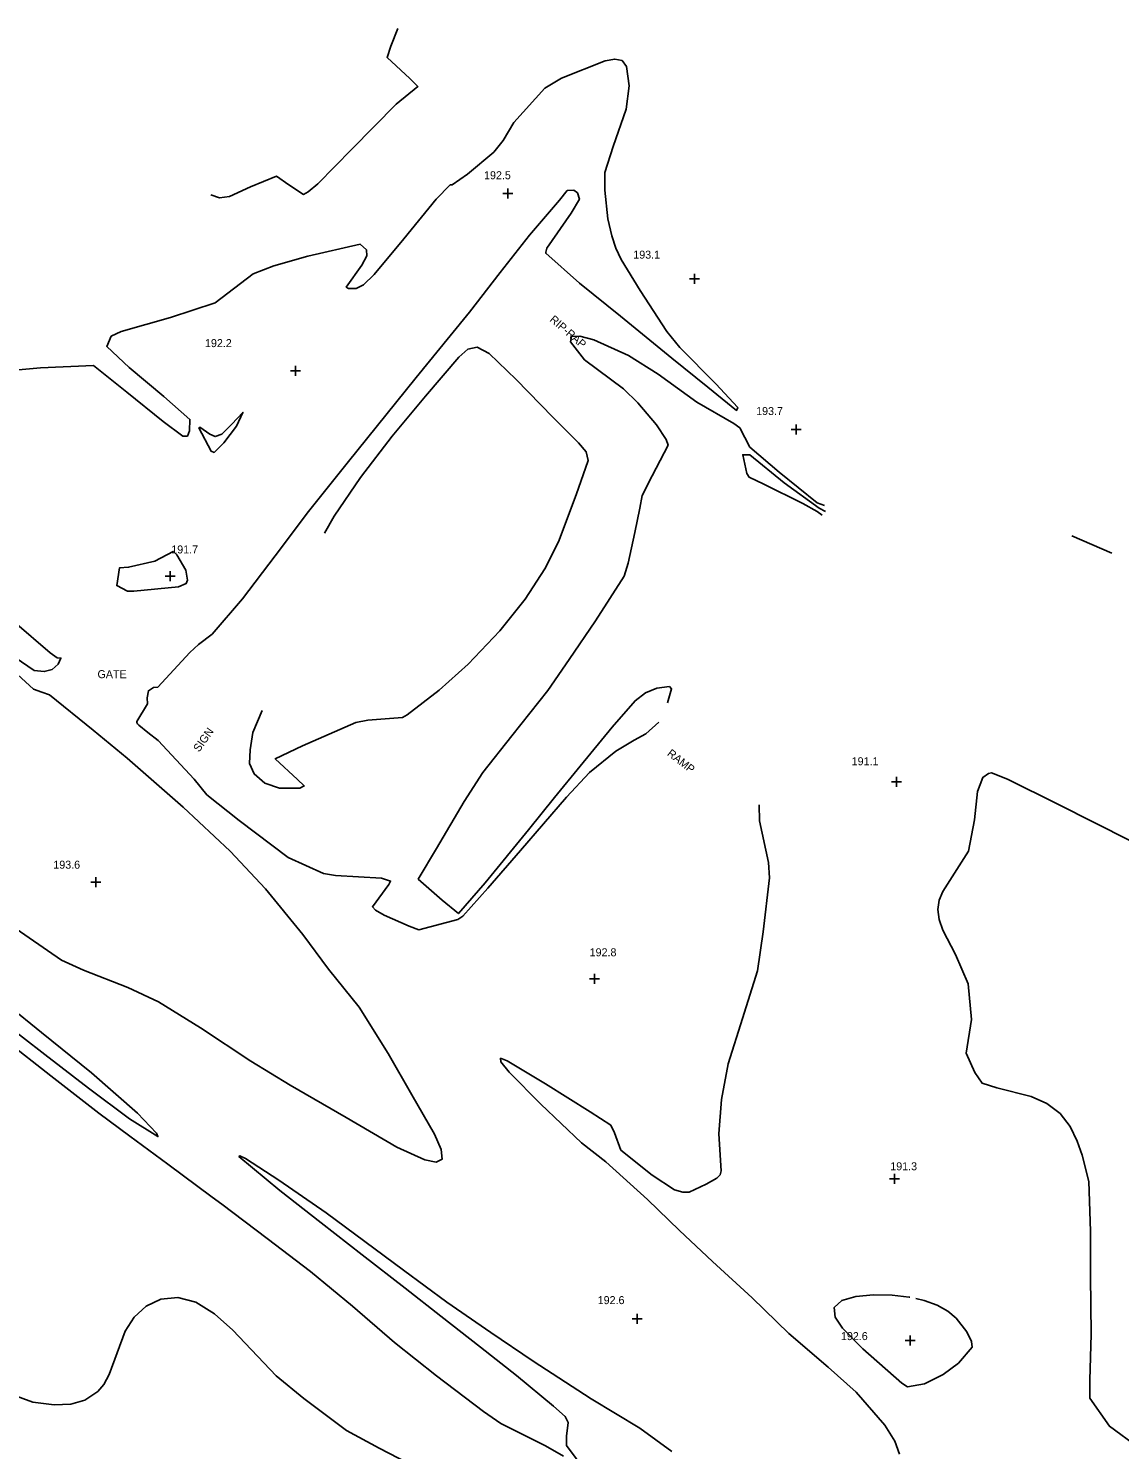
# Model space of a CAD drawing. Extents: x 1467615 to 2003689, y 770235 to 1108726.
# Drawn here: x 1994958.5 to 1995231.2, y 777132.3 to 777487.6 of the extents above; entities that cross this region are included whole.
import ezdxf

# ---------------------------------------------------------------- set-up
doc = ezdxf.new("R2010")
doc.units = 0
for name, color, linetype in [('RD_DTM_Minor1', 7, 'Continuous'), ('RD_DTM_Spot_Elev', 7, 'Continuous'), ('RD_TX_Misc1', 7, 'Continuous')]:
    doc.layers.add(name, color=color, linetype=linetype)

msp = doc.modelspace()

# ---------------------------------------------------------------- linework, layer by layer
at = {"layer": 'RD_DTM_Minor1'}
msp.add_line((1995219.32, 777360.71), (1995229.32, 777356.41), dxfattribs=at)
for points in [[(1995004.03, 777446.02), (1995006.26, 777445.24), (1995008.73, 777445.59), (1995013.96, 777448.01), (1995020.46, 777450.62), (1995023.59, 777448.46), (1995027.25, 777446.08), (1995028.37, 777446.72), (1995030.78, 777448.76), (1995039.35, 777457.45), (1995050.38, 777468.67), (1995055.83, 777473.11), (1995053.81, 777475.05), (1995048.11, 777480.32), (1995049.04, 777483.2), (1995050.78, 777487.59)], [(1994948.53, 777401.56), (1994961.49, 777402.72), (1994974.76, 777403.29), (1994983.11, 777396.65), (1994992.14, 777389.34), (1994997.1, 777385.68), (1994998.21, 777385.63), (1994998.77, 777386.96), (1994998.85, 777389.86), (1994992.35, 777395.6), (1994983.64, 777402.82), (1994978.07, 777408.08), (1994979.19, 777410.64), (1994981.62, 777411.82), (1994993.95, 777415.34), (1995005.14, 777418.99), (1995014.62, 777426.25), (1995019.85, 777428.27), (1995028.32, 777430.67), (1995041.38, 777433.62), (1995042.99, 777432.23), (1995043.1, 777430.73), (1995041.81, 777428.45), (1995037.91, 777422.92), (1995038.5, 777422.58), (1995040.42, 777422.59), (1995042.27, 777423.5), (1995044.9, 777426.06), (1995052.35, 777434.98), (1995060.44, 777444.88), (1995063.9, 777448.49), (1995064.37, 777448.52), (1995068.23, 777451.12), (1995074.81, 777456.65), (1995077.12, 777459.59), (1995079.83, 777464.09), (1995087.55, 777472.7), (1995091.72, 777475.2), (1995102.67, 777479.46), (1995105.03, 777479.95), (1995106.89, 777479.56), (1995108.01, 777478.04), (1995108.61, 777473.28), (1995107.9, 777467.41), (1995104.64, 777458.09), (1995102.59, 777451.54), (1995102.55, 777447.14), (1995103.28, 777439.98), (1995104.3, 777435.75), (1995105.32, 777432.69), (1995106.67, 777429.79), (1995111.4, 777422.07), (1995118.06, 777411.86), (1995121.32, 777407.85), (1995130.34, 777398.72), (1995135.77, 777392.83), (1995135.48, 777392.11), (1995128.29, 777397.94), (1995119.34, 777405.2), (1995106.49, 777415.63), (1995096.27, 777423.95), (1995087.81, 777431.37), (1995087.81, 777431.66), (1995088.1, 777432.69), (1995094.18, 777441.44), (1995096.23, 777444.89), (1995095.71, 777446.48), (1995094.82, 777447.12), (1995093.18, 777447.07), (1995091.19, 777444.69), (1995083.73, 777435.94), (1995076.37, 777426.6), (1995068.71, 777416.67), (1995063.87, 777410.73), (1995055.44, 777400.35), (1995047.79, 777390.92), (1995038.49, 777379.35), (1995028.52, 777366.79), (1995020.18, 777355.74), (1995012, 777345.03), (1995004.44, 777336.17), (1995000.95, 777333.56), (1994998.83, 777331.56), (1994990.82, 777322.88), (1994989.7, 777322.84), (1994988.46, 777322), (1994988.17, 777320.28), (1994988.25, 777318.75), (1994985.59, 777314.32), (1994985.57, 777314.08), (1994985.75, 777313.78), (1994986.08, 777313.45), (1994988.35, 777311.61), (1994990.88, 777309.54), (1994999.92, 777299.87), (1995003.04, 777296), (1995011.14, 777289.55), (1995023.43, 777280.35), (1995032.25, 777276.34), (1995035.25, 777275.83), (1995046.7, 777275.16), (1995049.01, 777274.42), (1995048.54, 777273.61), (1995044.47, 777268.03), (1995045.24, 777267.17), (1995047.38, 777265.88), (1995053.69, 777263.16), (1995056.04, 777262.23), (1995065.81, 777264.86), (1995067.09, 777265.65), (1995073.32, 777272.66), (1995081.49, 777282.1), (1995092.95, 777295.42), (1995098.71, 777301.56), (1995105.35, 777306.91), (1995109.86, 777309.63), (1995112.79, 777311.23), (1995116.05, 777314.2)], [(1995118.21, 777318.97), (1995119.25, 777322.46), (1995118.69, 777323.05), (1995115.56, 777322.67), (1995112.69, 777321.53), (1995110.13, 777319.53), (1995104.37, 777312.92), (1995096.39, 777303.18), (1995089.98, 777295.29), (1995083.45, 777287.25), (1995072.67, 777273.97), (1995065.97, 777266.29), (1995061.92, 777269.65), (1995055.94, 777274.92), (1995060.48, 777282.6), (1995067.38, 777294.36), (1995072.03, 777301.61), (1995079.34, 777310.77), (1995088.28, 777322.07), (1995093.61, 777329.81), (1995100.24, 777339.47), (1995107.36, 777350.67), (1995108.4, 777353.94), (1995110.04, 777361.56), (1995111.34, 777367.62), (1995111.92, 777370.82), (1995114.38, 777375.72), (1995118.39, 777383.42), (1995117.9, 777384.85), (1995115.46, 777388.46), (1995110.81, 777394.02), (1995107.19, 777397.47), (1995097.48, 777404.72), (1995094.01, 777409.27), (1995094.2, 777410.57), (1995096.3, 777410.66), (1995099.83, 777409.71), (1995108.51, 777405.86), (1995115.91, 777401.13), (1995125.55, 777394.2), (1995134.84, 777388.83), (1995136.29, 777387.75), (1995138.84, 777382.91), (1995146.18, 777376.62), (1995155.61, 777368.99), (1995157.5, 777368.3)], [(1995016.87, 777317.04), (1995014.58, 777311.55), (1995013.93, 777307.21), (1995013.77, 777303.79), (1995014.92, 777301.24), (1995017.58, 777298.9), (1995021.27, 777297.66), (1995026.28, 777297.68), (1995027.44, 777298.22), (1995025.71, 777299.85), (1995020.16, 777305.02), (1995026.96, 777308.22), (1995040.3, 777314.05), (1995043.29, 777314.66), (1995052, 777315.35), (1995053.11, 777315.98), (1995061.16, 777322.2), (1995068.38, 777328.66), (1995076.34, 777337), (1995082.68, 777344.94), (1995087.59, 777352.47), (1995090.95, 777359.25), (1995095.39, 777371.02), (1995098.37, 777379.56), (1995097.86, 777381.71), (1995096.01, 777384.03), (1995089.57, 777390.38), (1995080.43, 777399.84), (1995073.67, 777406.34), (1995070.68, 777407.89), (1995068.34, 777407.37), (1995066.06, 777405.41), (1995057.7, 777395.68), (1995049.36, 777385.7), (1995041.49, 777375.36), (1995034.94, 777365.67), (1995032.5, 777361.42)], [(1995001.34, 777387.88), (1995001.08, 777387.74), (1995004.14, 777381.91), (1995004.91, 777381.6), (1995007.34, 777383.98), (1995010.47, 777388.16), (1995012.08, 777391.58), (1995009.34, 777388.69), (1995006.85, 777386.14), (1995005.19, 777385.55), (1995003.79, 777386.15), (1995001.34, 777387.88)], [(1995156.92, 777365.93), (1995155.63, 777366.83), (1995152.03, 777368.8), (1995142.31, 777373.68), (1995138.64, 777375.4), (1995138.05, 777376.35), (1995137.02, 777381.02), (1995138.83, 777381.02), (1995147.36, 777374.02), (1995156.15, 777367.67), (1995157.75, 777366.82)], [(1994996.02, 777347.97), (1994984.79, 777346.93), (1994983.27, 777346.87), (1994980.55, 777348.31), (1994981.22, 777352.73), (1994983.53, 777352.89), (1994990.1, 777354.41), (1994994.67, 777356.86), (1994995.55, 777355.97), (1994997.78, 777352.15), (1994998.27, 777349.7), (1994997.92, 777348.86), (1994996.02, 777347.97)], [(1994955.14, 777330.36), (1994959.91, 777327.11), (1994962.41, 777326.81), (1994964.38, 777327.32), (1994965.88, 777328.63), (1994966.59, 777330.19), (1994965.66, 777330.27), (1994963.92, 777331.49), (1994954.98, 777339.2)], [(1994954.06, 777263.41), (1994966.72, 777254.62), (1994972.23, 777252.15), (1994983.35, 777247.85), (1994991, 777244.24), (1995001.46, 777237.71), (1995014.07, 777229.38), (1995023.88, 777223.39), (1995037.88, 777215.32), (1995050.53, 777207.92), (1995057.6, 777204.75), (1995060.41, 777204.19), (1995061.92, 777204.94), (1995061.68, 777207.35), (1995060, 777211.12), (1995054.34, 777221.01), (1995048.36, 777231.35), (1995041.13, 777242.87), (1995033.49, 777252.45), (1995027.05, 777261.05), (1995017.77, 777272.53), (1995008.94, 777281.88), (1994997.15, 777292.89), (1994983.18, 777305.18), (1994974.69, 777312.17), (1994963.74, 777320.96), (1994961.86, 777321.63), (1994959.73, 777322.42), (1994952.67, 777328.91)], [(1995236.01, 777132.83), (1995228.69, 777138.13), (1995223.83, 777145.2), (1995223.83, 777149.63), (1995224.15, 777161.17), (1995223.94, 777175.66), (1995223.94, 777186.93), (1995223.58, 777199.36), (1995221.9, 777205.88), (1995220.67, 777209.42), (1995218.88, 777213.06), (1995216.36, 777216.32), (1995213.04, 777218.8), (1995209.12, 777220.57), (1995200.53, 777222.71), (1995196.85, 777223.91), (1995195.09, 777226.56), (1995192.87, 777231.43), (1995194.2, 777239.83), (1995193.42, 777248.76), (1995190.24, 777256.09), (1995187.04, 777262.12), (1995186.14, 777264.79), (1995185.84, 777267.29), (1995186.14, 777269.64), (1995187.04, 777271.85), (1995193.46, 777281.91), (1995194.95, 777289.74), (1995195.72, 777296.82), (1995197.03, 777300.34), (1995198.5, 777301.36), (1995199.19, 777301.47), (1995203.24, 777299.89), (1995215.8, 777293.66), (1995233.93, 777284.46)], [(1995176.23, 777131.16), (1995175.09, 777134.4), (1995172.52, 777138.4), (1995165.37, 777146.65), (1995158.42, 777152.94), (1995148.57, 777161.35), (1995139.43, 777170.22), (1995129.47, 777179.36), (1995121.21, 777187.04), (1995113.2, 777194.84), (1995102.78, 777204.24), (1995096.74, 777208.97), (1995086.53, 777218.63), (1995078.66, 777226.69), (1995076.56, 777229.27), (1995076.52, 777230.12), (1995078.18, 777229.51), (1995087.7, 777223.71), (1995098.93, 777216.77), (1995104.09, 777213.38), (1995105.01, 777211.46), (1995106.55, 777207.18), (1995114.41, 777200.88), (1995119.97, 777197.28), (1995122.05, 777196.62), (1995123.68, 777196.68), (1995127.89, 777198.66), (1995130.56, 777200.14), (1995131.38, 777200.98), (1995131.68, 777201.97), (1995131.04, 777211.21), (1995131.72, 777219.83), (1995133.43, 777228.74), (1995136.97, 777240.06), (1995140.7, 777252.02), (1995142.14, 777261.77), (1995143.69, 777275.22), (1995143.45, 777279.07), (1995141.24, 777289.49), (1995141.12, 777293.48)], [(1994951.36, 777239.76), (1994962.59, 777231.07), (1994973.46, 777222.66), (1994983.7, 777215.03), (1994990.86, 777210.54), (1994990.5, 777211.41), (1994985.72, 777216.41), (1994974.21, 777226.49), (1994961.77, 777236.54), (1994953.31, 777243.41)], [(1994952.85, 777234.55), (1994964.08, 777225.76), (1994976.05, 777216.45), (1994983.85, 777210.65), (1994993.28, 777203.68), (1995004.39, 777195.43), (1995006.8, 777193.62)], [(1995097.85, 777126.86), (1995093.02, 777133.31), (1995092.95, 777135.66), (1995093.4, 777139.06), (1995092.63, 777140.54), (1995089.74, 777143.2), (1995080.52, 777150.8), (1995071.5, 777157.92), (1995061.6, 777165.69), (1995052.69, 777172.64), (1995041.93, 777181.01), (1995031.68, 777188.99), (1995021.29, 777197.11), (1995011.1, 777205.58), (1995011.28, 777205.77), (1995012.7, 777205.07), (1995021.05, 777199.62), (1995032.92, 777191.46), (1995042.57, 777184.31), (1995052.23, 777177.12), (1995063.05, 777169.2), (1995074.03, 777161.58), (1995084.66, 777154.37), (1995099.13, 777145.02), (1995111.33, 777137.63), (1995119.32, 777131.79)], [(1995006.8, 777193.62), (1995018.19, 777185.08), (1995028.96, 777176.83), (1995039.49, 777168.16), (1995050, 777159.1), (1995060.47, 777150.72), (1995072.2, 777141.84), (1995076.58, 777138.85), (1995087.69, 777133.26), (1995092.25, 777130.65)], [(1994954.54, 777145.98), (1994959.61, 777144.19), (1994964.91, 777143.47), (1994969.1, 777143.66), (1994972.54, 777144.7), (1994975.8, 777146.8), (1994977.3, 777148.58), (1994978.65, 777151.07), (1994982.67, 777161.91), (1994984.87, 777165.4), (1994987.88, 777168.18), (1994991.59, 777169.93), (1994995.81, 777170.35), (1995000.34, 777169.16), (1995004.99, 777166.23), (1995009.54, 777162.16), (1995020.42, 777150.72), (1995027.31, 777145.09), (1995037.96, 777137.04), (1995046.19, 777132.68), (1995055.78, 777127.7)], [(1995178.8, 777170.4), (1995178.68, 777170.43), (1995174.41, 777170.92), (1995169.75, 777171), (1995165.3, 777170.57), (1995161.78, 777169.54), (1995159.9, 777167.84), (1995160.14, 777165.43), (1995161.94, 777162.64), (1995167.03, 777157.46), (1995176.82, 777148.87), (1995178.25, 777148.02), (1995182.45, 777148.78), (1995187.18, 777151.1), (1995190.97, 777153.91)], [(1995190.97, 777153.91), (1995194.42, 777157.95), (1995194.21, 777159.29), (1995193.04, 777161.73), (1995190.35, 777165.19), (1995188.27, 777166.89), (1995185.63, 777168.37), (1995182.42, 777169.57), (1995180.32, 777170.05)]]:
    msp.add_lwpolyline(points, dxfattribs=at)
at = {"layer": 'RD_DTM_Spot_Elev'}
for p, q in [((1995078.29, 777445.06), (1995078.29, 777447.56)), ((1995077.04, 777446.31), (1995079.54, 777446.31)), ((1995125, 777423.75), (1995125, 777426.25)), ((1995123.75, 777425), (1995126.25, 777425)), ((1995023.98, 777402.03), (1995026.48, 777402.03)), ((1995025.23, 777400.78), (1995025.23, 777403.28)), ((1995149.11, 777387.34), (1995151.61, 777387.34)), ((1995150.36, 777386.09), (1995150.36, 777388.59)), ((1994993.93, 777349.37), (1994993.93, 777351.87)), ((1994992.68, 777350.62), (1994995.18, 777350.62)), ((1995174.21, 777299.24), (1995176.71, 777299.24)), ((1995175.46, 777297.99), (1995175.46, 777300.49)), ((1994974.1, 777274.17), (1994976.6, 777274.17)), ((1994975.35, 777272.92), (1994975.35, 777275.42)), ((1995098.75, 777250), (1995101.25, 777250)), ((1995100, 777248.75), (1995100, 777251.25)), ((1995173.75, 777200), (1995176.25, 777200)), ((1995175, 777198.75), (1995175, 777201.25)), ((1995109.42, 777164.99), (1995111.92, 777164.99)), ((1995110.67, 777163.74), (1995110.67, 777166.24)), ((1995177.66, 777159.57), (1995180.16, 777159.57)), ((1995178.91, 777158.32), (1995178.91, 777160.82))]:
    msp.add_line(p, q, dxfattribs=at)

# ---------------------------------------------------------------- texts
for s, p in [('192.5', (1995072.37, 777449.89)), ('193.1', (1995109.68, 777430.04)), ('192.2', (1995002.61, 777407.93)), ('193.7', (1995140.39, 777390.94)), ('191.7', (1994994.18, 777356.34)), ('191.1', (1995164.27, 777303.39)), ('193.6', (1994964.7, 777277.53)), ('192.8', (1995098.77, 777255.63)), ('191.3', (1995173.92, 777202.13)), ('192.6', (1995100.78, 777168.67)), ('192.6', (1995161.59, 777159.68))]:
    msp.add_text(s, height=2, dxfattribs=at).set_placement(p)
at = {"layer": 'RD_TX_Misc1'}
for s, rotation, p in [('RIP-RAP', 319.2963, (1995088.62, 777414.55)), ('SIGN', 54.6599, (1995001.13, 777306.53)), ('RAMP', 321.9952, (1995117.98, 777306.01))]:
    msp.add_text(s, height=2, rotation=rotation, dxfattribs=at).set_placement(p)
msp.add_text('GATE', height=2, dxfattribs=at).set_placement((1994975.74, 777325.16))

doc.saveas('drawing.dxf')
